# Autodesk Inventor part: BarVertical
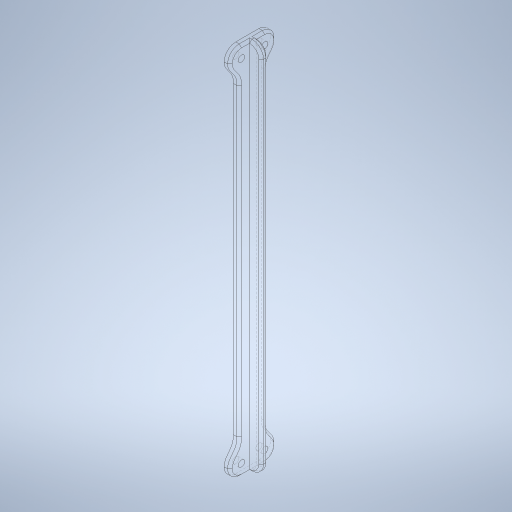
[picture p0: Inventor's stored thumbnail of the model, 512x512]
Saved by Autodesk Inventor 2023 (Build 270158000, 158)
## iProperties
Created: 2023-10
Part Number: BarVertical
Material: Aluminum 7075
Document SubType Name: Modeling
Designer: tornqvih
Density: 2.81 g/cm^3
Appearance: Satin - Brushed Heavy
Mass: 203.782 g
Surface Area: 251.708 cm^2
Volume: 72.5202 cm^3
Author: tornqvih
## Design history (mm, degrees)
sketch "Sketch1"
  geometry: L1 (131, -12)-(-131, -12); L2 (-131, 12)-(131, 12); L3 (0, -30.899)-(0, 30.899) reference; L4 (-228.299, 0)-(228.299, 0) reference; L5 (161, 10)-(161, -10); L6 (-161, 10)-(-161, -10); A1 r 10 centre (151, 10) between (161, 10) and (151, 20); A2 r 10 centre (151, -10) between (151, -20) and (161, -10); A3 r 10 centre (-151, 10) between (-151, 20) and (-161, 10); A4 r 10 centre (-151, -10) between (-161, -10) and (-151, -20); 1 further point
  constraints: 11 symmetric about line, 8 end point, 8 point on circle, 4 centre point, 4 horizontal, 1 horizontal alignment, 1 vertical, 1 vertical alignment, 12 other
  dimensions: "d22" = 12 distance between parallel lines of L4 L2; "d24" = 10 radius of A2; "d25" = 151 distance from line of L3 A2.centre; "d28" = 131 distance from line of L3 L1.start; "d34" = 10 distance from line of L4 A2.centre
extrude "Extrusion1" new body sketch "Sketch1" distance "d5" = 5; taper "d6" = 0 deg
sketch "Sketch2"
  geometry: L1 (28, 0)-(-28, 0) reference; L2 (0, -226.2)-(0, 230.2) reference; L3 (20, 145)-(20, 165) reference; L4 (20, 165)-(-20, 165) reference; 5 further points
  constraints: 3 symmetric about line
  dimensions: "d20" = 10 distance from line of L2 point (10, 151); "d21" = 151 distance from line of L1 point (10, 151)
hole "Hole1" sketch "Sketch2" at (10, 151), (-10, 151), (10, -151), (-10, -151) diameter "d9" = 5.5; stored, may be unused: countersink angle "d13" = 90 deg, drill point angle "d15" = 118 deg; dims "d10" = 6, "d11" = 4, "d12" = 2, "d14" = 8
sketch "Sketch3"
  geometry: L1 (0, 151)-(5, 151) reference; L2 (0, 161)-(5, 161) reference; L3 (0, -151)-(5, -151) reference; L4 (5, -161)-(5, -151) reference; L5 (15, 151)-(15, -151); L6 (5, 161)-(5, -161); A1 r 10 centre (5, 151) between (15, 151) and (5, 161); A2 r 10 centre (5, -151) between (5, -161) and (15, -151); 2 further points
  constraints: 5 point on circle, 4 end point, 2 centre point, 1 horizontal alignment, 1 parallel, 1 vertical
extrude "Extrusion2" join sketch "Sketch3" stored distance "d29" = 6; taper "d30" = 0 deg
chamfer "Chamfer1" distance "d31" = 2; stored, may be unused: second distance "d32" = 2, angle "d33" = 45 deg
body "Solid1"
